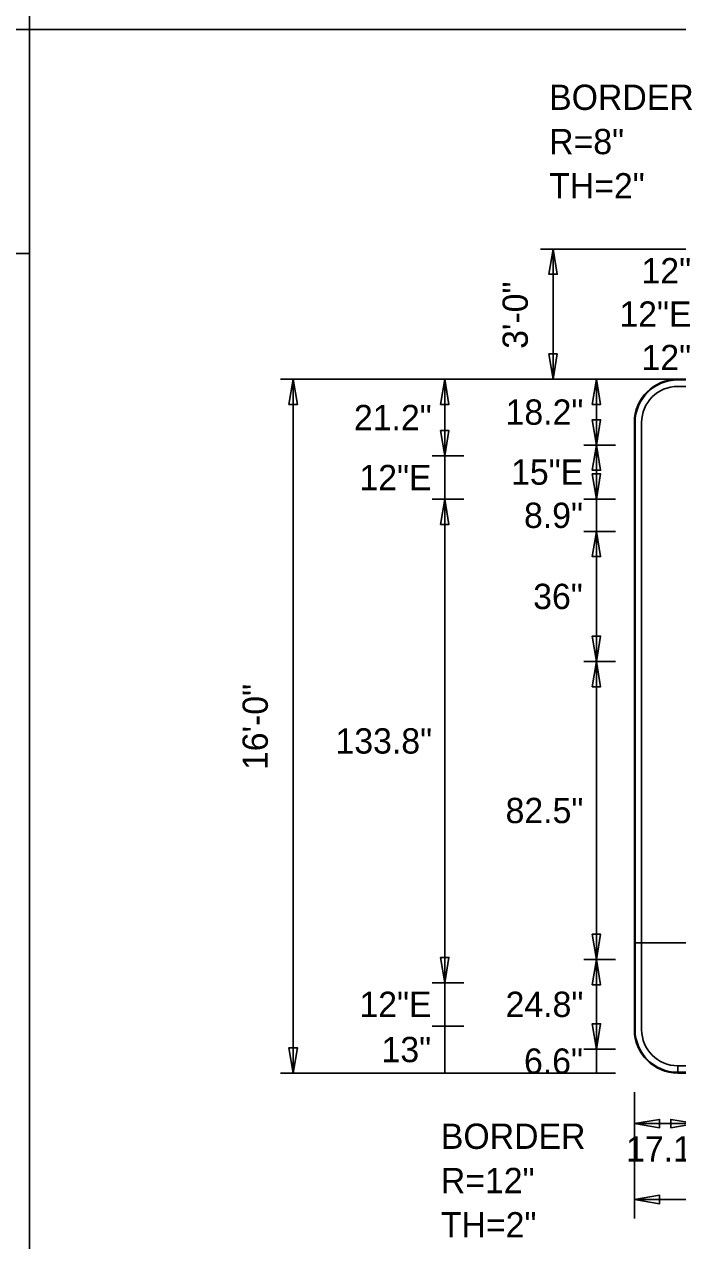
# Model space of a CAD drawing. Extents: x 2149934 to 2150188, y 145113 to 145238.
# Drawn here: x 2150076.2 to 2150091.28, y 145139.02 to 145167.07 of the extents above; entities that cross this region are included whole.
import ezdxf

# ---------------------------------------------------------------- set-up
doc = ezdxf.new("R2010")
doc.units = 0
for name, color, linetype in [('GSBWFILL', 7, 'Continuous'), ('GSCOLORFILL', 7, 'Continuous'), ('GSDIMS', 7, 'Continuous'), ('GSOUTLINE', 7, 'Continuous'), ('Level 1', 7, 'Continuous')]:
    doc.layers.add(name, color=color, linetype=linetype)

msp = doc.modelspace()

# ---------------------------------------------------------------- linework, layer by layer
at = {"layer": 'GSBWFILL'}
for p, q in [((2150104.779, 145158.883), (2150091.279, 145158.883)), ((2150091.279, 145158.716), (2150104.779, 145158.716)), ((2150090.279, 145157.883), (2150090.279, 145143.883)), ((2150090.445, 145143.883), (2150090.445, 145157.883)), ((2150090.279, 145143.883), (2150090.279, 145145.883)), ((2150090.279, 145145.883), (2150090.445, 145145.883)), ((2150105.779, 145145.883), (2150090.279, 145145.883)), ((2150090.279, 145145.883), (2150090.279, 145143.883)), ((2150090.445, 145145.883), (2150090.445, 145145.717)), ((2150090.445, 145145.717), (2150090.445, 145143.883)), ((2150091.279, 145142.883), (2150091.279, 145143.05)), ((2150091.279, 145143.05), (2150104.779, 145143.05)), ((2150104.779, 145142.883), (2150091.279, 145142.883)), ((2150091.279, 145142.883), (2150104.779, 145142.883))]:
    msp.add_line(p, q, dxfattribs=at)
for centre, radius, start, end in [((2150091.279, 145157.883), 1, 90, 180), ((2150091.279, 145157.883), 0.833, 90, 180), ((2150091.279, 145143.883), 1, 180, 270), ((2150091.279, 145143.883), 1, 180, 270), ((2150091.279, 145143.883), 1, 180, 270), ((2150091.279, 145143.883), 0.833, 180, 270), ((2150091.279, 145143.883), 0.833, 180, 270)]:
    msp.add_arc(centre, radius, start, end, dxfattribs=at)
at = {"layer": 'GSCOLORFILL'}
for p, q in [((2150104.779, 145158.883), (2150091.279, 145158.883)), ((2150104.779, 145158.883), (2150091.279, 145158.883)), ((2150104.779, 145158.883), (2150091.279, 145158.883)), ((2150091.279, 145158.866), (2150104.779, 145158.866)), ((2150091.279, 145158.716), (2150104.779, 145158.716)), ((2150090.279, 145157.883), (2150090.279, 145143.883)), ((2150090.279, 145157.883), (2150090.279, 145143.883)), ((2150090.279, 145157.883), (2150090.279, 145143.883)), ((2150090.295, 145143.883), (2150090.295, 145157.883)), ((2150090.445, 145143.883), (2150090.445, 145157.883)), ((2150105.779, 145145.883), (2150090.279, 145145.883)), ((2150090.279, 145145.883), (2150090.279, 145143.883)), ((2150090.279, 145143.883), (2150090.279, 145145.883)), ((2150090.279, 145145.883), (2150090.445, 145145.883)), ((2150090.279, 145143.883), (2150090.279, 145145.883)), ((2150090.279, 145145.883), (2150090.295, 145145.883)), ((2150090.295, 145145.883), (2150090.295, 145145.867)), ((2150090.295, 145145.867), (2150090.295, 145143.883)), ((2150090.445, 145145.883), (2150090.445, 145145.717)), ((2150090.445, 145145.717), (2150090.445, 145143.883)), ((2150091.279, 145142.883), (2150091.279, 145143.05)), ((2150091.279, 145143.05), (2150104.779, 145143.05)), ((2150091.279, 145142.883), (2150091.279, 145142.9)), ((2150091.279, 145142.9), (2150104.779, 145142.9)), ((2150091.279, 145142.883), (2150104.779, 145142.883)), ((2150091.279, 145142.883), (2150104.779, 145142.883)), ((2150104.779, 145142.883), (2150091.279, 145142.883)), ((2150104.779, 145142.883), (2150091.279, 145142.883))]:
    msp.add_line(p, q, dxfattribs=at)
for centre, radius, start, end in [((2150091.279, 145157.883), 1, 90, 180), ((2150091.279, 145157.883), 1, 90, 180), ((2150091.279, 145157.883), 1, 90, 180), ((2150091.279, 145157.883), 0.983, 90, 180), ((2150091.279, 145157.883), 0.833, 90, 180), ((2150091.279, 145143.883), 1, 180, 270), ((2150091.279, 145143.883), 1, 180, 270), ((2150091.279, 145143.883), 1, 180, 270), ((2150091.279, 145143.883), 1, 180, 270), ((2150091.279, 145143.883), 1, 180, 270), ((2150091.279, 145143.883), 1, 180, 270), ((2150091.279, 145143.883), 0.983, 180, 270), ((2150091.279, 145143.883), 0.983, 180, 270), ((2150091.279, 145143.883), 0.833, 180, 270), ((2150091.279, 145143.883), 0.833, 180, 270)]:
    msp.add_arc(centre, radius, start, end, dxfattribs=at)
at = {"layer": 'GSDIMS'}
for p, q in [((2150088.841, 145161.884), (2150088.112, 145161.884)), ((2150088.403, 145158.883), (2150088.403, 145161.884)), ((2150092.341, 145161.884), (2150088.841, 145161.884)), ((2150082.841, 145158.883), (2150082.112, 145158.883)), ((2150082.404, 145142.883), (2150082.404, 145158.883)), ((2150089.841, 145158.883), (2150082.841, 145158.883)), ((2150086.341, 145158.883), (2150085.612, 145158.883)), ((2150085.904, 145157.115), (2150085.904, 145158.883)), ((2150088.841, 145158.883), (2150088.112, 145158.883)), ((2150092.341, 145158.883), (2150088.841, 145158.883)), ((2150089.841, 145158.883), (2150089.112, 145158.883)), ((2150089.404, 145157.365), (2150089.404, 145158.883)), ((2150089.841, 145157.365), (2150089.112, 145157.365)), ((2150089.841, 145157.365), (2150089.112, 145157.365)), ((2150089.404, 145157.365), (2150089.404, 145156.115)), ((2150086.341, 145157.115), (2150085.612, 145157.115)), ((2150086.341, 145157.115), (2150085.612, 145157.115)), ((2150085.904, 145157.115), (2150085.904, 145156.115)), ((2150086.341, 145156.115), (2150085.612, 145156.115)), ((2150086.341, 145156.115), (2150085.612, 145156.115)), ((2150085.904, 145144.966), (2150085.904, 145156.115)), ((2150089.841, 145156.115), (2150089.112, 145156.115)), ((2150089.841, 145156.115), (2150089.112, 145156.115)), ((2150089.404, 145155.373), (2150089.404, 145156.115)), ((2150089.841, 145155.373), (2150089.112, 145155.373)), ((2150089.841, 145155.373), (2150089.112, 145155.373)), ((2150089.404, 145155.373), (2150089.404, 145152.373)), ((2150089.841, 145152.373), (2150089.112, 145152.373)), ((2150089.841, 145152.373), (2150089.112, 145152.373)), ((2150089.404, 145145.5), (2150089.404, 145152.373)), ((2150089.841, 145145.5), (2150089.112, 145145.5)), ((2150089.841, 145145.5), (2150089.112, 145145.5)), ((2150089.404, 145145.5), (2150089.404, 145143.433)), ((2150086.341, 145144.966), (2150085.612, 145144.966)), ((2150086.341, 145144.966), (2150085.612, 145144.966)), ((2150085.904, 145144.966), (2150085.904, 145143.966)), ((2150086.341, 145143.966), (2150085.612, 145143.966)), ((2150086.341, 145143.966), (2150085.612, 145143.966)), ((2150085.904, 145142.883), (2150085.904, 145143.966)), ((2150089.841, 145143.433), (2150089.112, 145143.433)), ((2150089.841, 145143.433), (2150089.112, 145143.433)), ((2150089.404, 145142.883), (2150089.404, 145143.433)), ((2150082.841, 145142.883), (2150082.112, 145142.883)), ((2150089.841, 145142.883), (2150082.841, 145142.883)), ((2150086.341, 145142.883), (2150085.612, 145142.883)), ((2150089.841, 145142.883), (2150089.112, 145142.883)), ((2150090.279, 145142.445), (2150090.279, 145139.529)), ((2150090.279, 145142.154), (2150090.279, 145141.425)), ((2150090.279, 145141.716), (2150091.7, 145141.716)), ((2150090.279, 145140.404), (2150090.279, 145139.675)), ((2150090.279, 145139.966), (2150105.779, 145139.966))]:
    msp.add_line(p, q, dxfattribs=at)
for points in [[(2150088.403, 145161.884), (2150088.5, 145161.301), (2150088.306, 145161.301)], [(2150088.403, 145158.883), (2150088.5, 145159.466), (2150088.306, 145159.466)], [(2150082.404, 145158.883), (2150082.501, 145158.3), (2150082.306, 145158.3)], [(2150085.904, 145158.883), (2150086.001, 145158.3), (2150085.806, 145158.3)], [(2150089.404, 145158.883), (2150089.501, 145158.3), (2150089.306, 145158.3)], [(2150085.904, 145157.115), (2150086.001, 145157.698), (2150085.806, 145157.698)], [(2150089.404, 145157.365), (2150089.501, 145157.948), (2150089.306, 145157.948)], [(2150089.404, 145157.365), (2150089.501, 145156.782), (2150089.306, 145156.782)], [(2150089.404, 145156.115), (2150089.501, 145156.698), (2150089.306, 145156.698)], [(2150085.904, 145156.115), (2150086.001, 145155.532), (2150085.806, 145155.532)], [(2150089.404, 145155.373), (2150089.501, 145154.79), (2150089.306, 145154.79)], [(2150089.404, 145152.373), (2150089.501, 145152.957), (2150089.306, 145152.957)], [(2150089.404, 145152.373), (2150089.501, 145151.79), (2150089.306, 145151.79)], [(2150089.404, 145145.5), (2150089.501, 145146.083), (2150089.306, 145146.083)], [(2150085.904, 145144.966), (2150086.001, 145145.55), (2150085.806, 145145.55)], [(2150089.404, 145145.5), (2150089.501, 145144.917), (2150089.306, 145144.917)], [(2150089.404, 145143.433), (2150089.501, 145144.017), (2150089.306, 145144.017)], [(2150082.404, 145142.883), (2150082.501, 145143.466), (2150082.306, 145143.466)], [(2150090.279, 145141.716), (2150090.862, 145141.813), (2150090.862, 145141.619)], [(2150091.7, 145141.716), (2150091.117, 145141.813), (2150091.117, 145141.619)], [(2150090.279, 145139.966), (2150090.862, 145140.063), (2150090.862, 145139.869)]]:
    msp.add_lwpolyline(points, close=True, dxfattribs=at)
at = {"layer": 'GSOUTLINE'}
for p, q in [((2150104.779, 145158.883), (2150091.279, 145158.883)), ((2150104.779, 145158.716), (2150091.279, 145158.716)), ((2150090.279, 145157.883), (2150090.279, 145143.883)), ((2150090.445, 145157.883), (2150090.445, 145143.883)), ((2150090.279, 145143.883), (2150090.279, 145145.883)), ((2150090.279, 145145.883), (2150090.445, 145145.883)), ((2150105.779, 145145.883), (2150090.279, 145145.883)), ((2150090.279, 145145.883), (2150090.279, 145143.883)), ((2150090.445, 145145.883), (2150090.445, 145145.717)), ((2150090.445, 145145.717), (2150090.445, 145143.883)), ((2150091.279, 145143.05), (2150104.779, 145143.05)), ((2150091.279, 145143.05), (2150104.779, 145143.05)), ((2150091.279, 145142.883), (2150104.779, 145142.883)), ((2150104.779, 145142.883), (2150091.279, 145142.883)), ((2150091.279, 145142.883), (2150104.779, 145142.883))]:
    msp.add_line(p, q, dxfattribs=at)
for centre, radius, start, end in [((2150091.279, 145157.883), 1, 90, 180), ((2150091.279, 145157.883), 0.833, 90, 180), ((2150091.279, 145143.883), 1, 180, 270), ((2150091.279, 145143.883), 1, 180, 270), ((2150091.279, 145143.883), 1, 180, 270), ((2150091.279, 145143.883), 0.833, 180, 270), ((2150091.279, 145143.883), 0.833, 180, 270)]:
    msp.add_arc(centre, radius, start, end, dxfattribs=at)
at = {"layer": 'Level 1'}
for p, q in [((2150076.316, 145216.512), (2150076.316, 145117.388)), ((2150135.447, 145166.95), (2150017.557, 145166.95)), ((2150062.21, 145161.778), (2150076.316, 145161.778))]:
    msp.add_line(p, q, dxfattribs=at)

# ---------------------------------------------------------------- texts
at = {"layer": 'GSDIMS'}
for s, p in [('BORDER', (2150088.312, 145165.092)), ('R=8"', (2150088.312, 145164.071)), ('TH=2"', (2150088.312, 145163.051)), ('12"', (2150090.444, 145161.092)), ('12"E', (2150089.933, 145160.092)), ('12"', (2150090.444, 145159.091)), ('21.2"', (2150083.807, 145157.707)), ('18.2"', (2150087.307, 145157.832)), ('12"E', (2150083.934, 145156.323)), ('15"E', (2150087.434, 145156.448)), ('8.9"', (2150087.732, 145155.452)), ('36"', (2150087.944, 145153.582)), ('133.8"', (2150083.382, 145150.249)), ('82.5"', (2150087.307, 145148.645)), ('12"E', (2150083.934, 145144.175)), ('24.8"', (2150087.307, 145144.175)), ('13"', (2150084.444, 145143.133)), ('6.6"', (2150087.732, 145142.866)), ('BORDER', (2150085.813, 145141.133)), ('17.1"', (2150090.087, 145140.841)), ('R=12"', (2150085.813, 145140.112)), ('TH=2"', (2150085.813, 145139.091))]:
    msp.add_text(s, height=0.5833, dxfattribs=at).set_placement(p)
for s, p in [('3\'-0"', (2150087.82, 145159.582)), ('16\'-0"', (2150081.82, 145149.869))]:
    msp.add_text(s, height=0.5833, rotation=90, dxfattribs=at).set_placement(p)

doc.saveas('drawing.dxf')
